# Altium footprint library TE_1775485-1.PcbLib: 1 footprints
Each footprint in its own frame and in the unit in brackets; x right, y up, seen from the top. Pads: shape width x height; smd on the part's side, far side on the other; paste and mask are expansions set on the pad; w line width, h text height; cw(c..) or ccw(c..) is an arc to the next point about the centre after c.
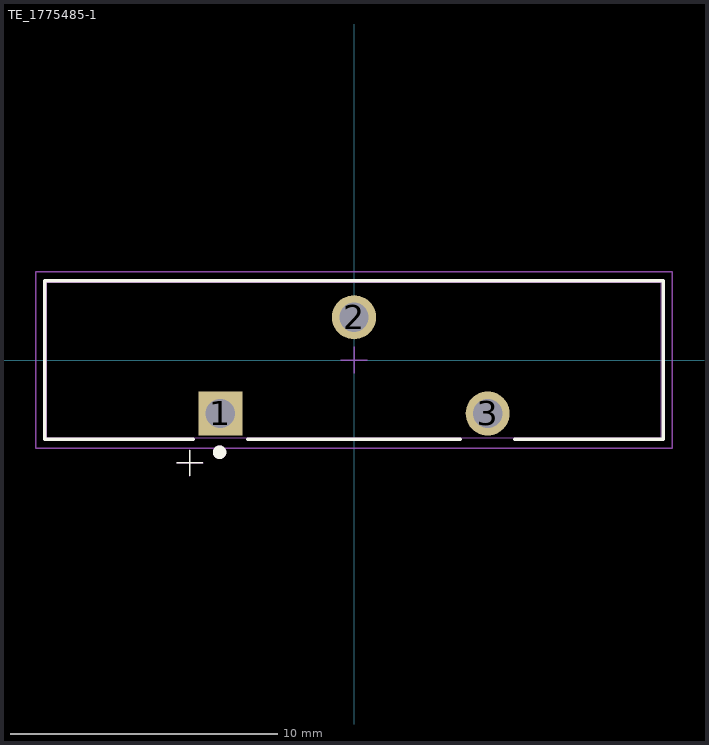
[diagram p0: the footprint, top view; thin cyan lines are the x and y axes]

## TE_1775485-1 [mm] "Battery Holder; 3 pin, 23.000 mm L X 5.800 mm W X 21.000 mm H body"
height 21
pads (3):
  rect 1.65x1.65 / inner round 1.65 / far side rect 1.65x1.65 hole 1.1 paste-2539.97: 1(-5,-2)
  round 1.65 hole 1.1 paste-2539.97: 2(0,1.6) 3(5,-2)
Top Overlay:
  circle w0.254: c-5.028,-3.45 r0.127
  lines w0.05: -6.621,-3.85 -5.655,-3.85 ; -6.138,-4.333 -6.138,-3.367
  lines w0.127: -6.016,-2.964 -11.564,-2.964 -11.564,2.964 11.564,2.964 11.564,-2.964 6.016,-2.964 ; -3.985,-2.964 3.985,-2.964
Mechanical 11:
  circle w0.25: c-5.028,-3.45 r0.125
  lines w0.025: -6.634,-3.85 -5.643,-3.85 ; -6.138,-4.346 -6.138,-3.355 ; -11.5,-2.9 11.5,-2.9 11.5,2.9 -11.5,2.9 -11.5,-2.9
  text ".Designator" at -5.078,-0.339 h1.02
Mechanical 15:
  lines w0.05: -0.5,0 0.5,0 ; 0,-0.5 0,0.5 ; -11.9,-3.3 11.9,-3.3 11.9,3.3 -11.9,3.3 -11.9,-3.3
3D body "1775485-1 (2).step": height 18.51, standoff -3, extent -11.5,-2.9 11.495,2.9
